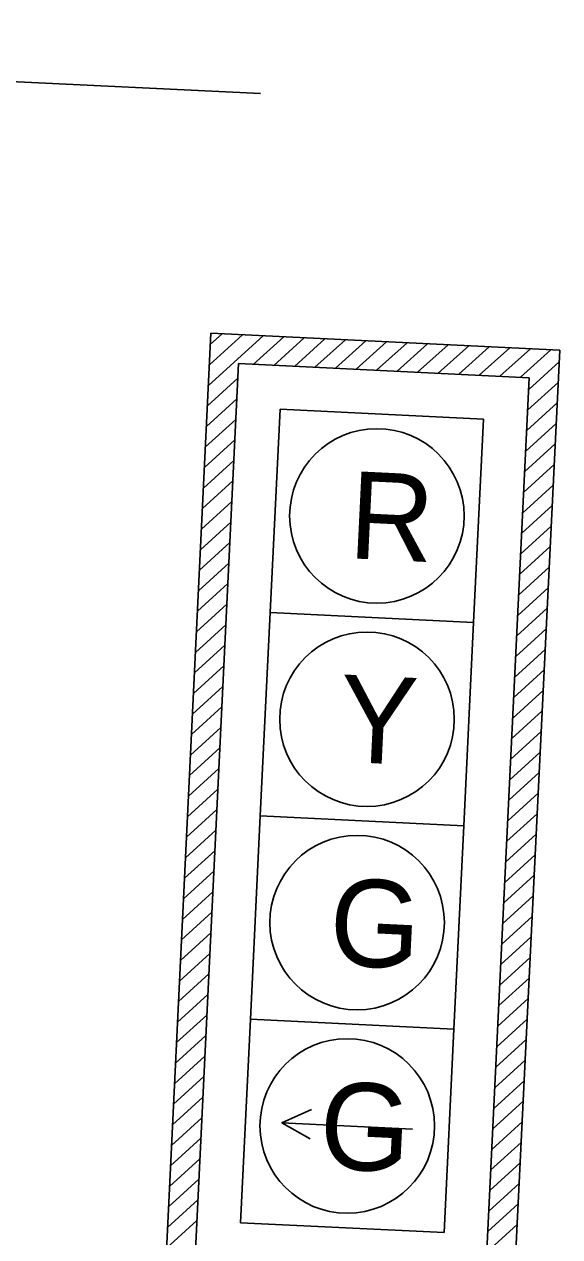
# Model space of a CAD drawing. Extents: x 662220 to 671027, y 641390 to 743815.
# Drawn here: x 662575.9 to 662612.7, y 642642.2 to 642725.6 of the extents above; entities that cross this region are included whole.
import ezdxf

# ---------------------------------------------------------------- set-up
doc = ezdxf.new("R2010")
doc.units = 0
doc.layers.add('R_Proposed Road Annot', color=7, linetype='Continuous')

msp = doc.modelspace()

# ---------------------------------------------------------------- linework, layer by layer
at = {"layer": 'R_Proposed Road Annot'}
for p, q in [((662494.01, 642725.551), (662592.08, 642720.789)), ((662588.684, 642704.307), (662585.483, 642638.385)), ((662588.51, 642700.718), (662592.273, 642704.133)), ((662588.578, 642702.131), (662590.86, 642704.201)), ((662588.647, 642703.543), (662589.448, 642704.27)), ((662612.656, 642703.143), (662588.684, 642704.307)), ((662591.591, 642702.163), (662593.685, 642704.064)), ((662593.003, 642702.095), (662595.098, 642703.995)), ((662594.416, 642702.026), (662596.51, 642703.927)), ((662595.828, 642701.958), (662597.923, 642703.858)), ((662597.241, 642701.889), (662599.335, 642703.79)), ((662598.653, 642701.82), (662600.748, 642703.721)), ((662600.066, 642701.752), (662602.16, 642703.652)), ((662601.478, 642701.683), (662603.573, 642703.584)), ((662602.891, 642701.615), (662604.986, 642703.515)), ((662604.303, 642701.546), (662606.398, 642703.447)), ((662605.716, 642701.477), (662607.811, 642703.378)), ((662607.129, 642701.409), (662609.223, 642703.309)), ((662608.541, 642701.34), (662610.636, 642703.241)), ((662609.454, 642637.22), (662612.656, 642703.143)), ((662609.954, 642701.272), (662612.048, 642703.172)), ((662610.522, 642700.437), (662612.617, 642702.338)), ((662588.441, 642699.306), (662590.536, 642701.206)), ((662610.453, 642699.024), (662612.548, 642700.925)), ((662588.372, 642697.893), (662590.467, 642699.794)), ((662610.385, 642697.612), (662612.479, 642699.512)), ((662593.435, 642699.07), (662592.756, 642685.087)), ((662593.435, 642699.07), (662607.419, 642698.391)), ((662588.304, 642696.48), (662590.398, 642698.381)), ((662607.419, 642698.391), (662606.74, 642684.408)), ((662610.316, 642696.199), (662612.411, 642698.1)), ((662588.235, 642695.068), (662590.33, 642696.969)), ((662610.248, 642694.787), (662612.342, 642696.687)), ((662588.167, 642693.655), (662590.261, 642695.556)), ((662610.179, 642693.374), (662612.274, 642695.275)), ((662588.098, 642692.243), (662590.193, 642694.143)), ((662610.11, 642691.962), (662612.205, 642693.862)), ((662588.029, 642690.83), (662590.124, 642692.731)), ((662610.042, 642690.549), (662612.136, 642692.45)), ((662587.961, 642689.418), (662590.056, 642691.318)), ((662609.973, 642689.137), (662612.068, 642691.037)), ((662587.892, 642688.005), (662589.987, 642689.906)), ((662609.905, 642687.724), (662611.999, 642689.625)), ((662587.824, 642686.593), (662589.918, 642688.493)), ((662609.836, 642686.311), (662611.931, 642688.212)), ((662587.755, 642685.18), (662589.85, 642687.081)), ((662609.767, 642684.899), (662611.862, 642686.8)), ((662587.687, 642683.768), (662589.781, 642685.668)), ((662609.699, 642683.486), (662611.793, 642685.387)), ((662592.756, 642685.087), (662592.077, 642671.103)), ((662592.756, 642685.087), (662606.74, 642684.408)), ((662587.618, 642682.355), (662589.713, 642684.256)), ((662606.74, 642684.408), (662606.061, 642670.424)), ((662609.63, 642682.074), (662611.725, 642683.974)), ((662587.549, 642680.942), (662589.644, 642682.843)), ((662609.562, 642680.661), (662611.656, 642682.562)), ((662587.481, 642679.53), (662589.575, 642681.431)), ((662609.493, 642679.249), (662611.588, 642681.149)), ((662587.412, 642678.117), (662589.507, 642680.018)), ((662609.424, 642677.836), (662611.519, 642679.737)), ((662587.344, 642676.705), (662589.438, 642678.605)), ((662609.356, 642676.424), (662611.45, 642678.324)), ((662587.275, 642675.292), (662589.37, 642677.193)), ((662609.287, 642675.011), (662611.382, 642676.912)), ((662587.206, 642673.88), (662589.301, 642675.78)), ((662609.219, 642673.598), (662611.313, 642675.499)), ((662587.138, 642672.467), (662589.232, 642674.368)), ((662609.15, 642672.186), (662611.245, 642674.087)), ((662587.069, 642671.055), (662589.164, 642672.955)), ((662609.081, 642670.773), (662611.176, 642672.674)), ((662587.001, 642669.642), (662589.095, 642671.543)), ((662592.077, 642671.103), (662591.398, 642657.12)), ((662592.077, 642671.103), (662606.061, 642670.424)), ((662609.013, 642669.361), (662611.108, 642671.261)), ((662606.061, 642670.424), (662605.382, 642656.441)), ((662586.932, 642668.229), (662589.027, 642670.13)), ((662608.944, 642667.948), (662611.039, 642669.849)), ((662586.863, 642666.817), (662588.958, 642668.718)), ((662608.876, 642666.536), (662610.97, 642668.436)), ((662586.795, 642665.404), (662588.889, 642667.305)), ((662608.807, 642665.123), (662610.902, 642667.024)), ((662586.726, 642663.992), (662588.821, 642665.892)), ((662608.738, 642663.711), (662610.833, 642665.611)), ((662586.658, 642662.579), (662588.752, 642664.48)), ((662608.67, 642662.298), (662610.765, 642664.199)), ((662586.589, 642661.167), (662588.684, 642663.067)), ((662608.601, 642660.886), (662610.696, 642662.786)), ((662586.52, 642659.754), (662588.615, 642661.655)), ((662608.533, 642659.473), (662610.627, 642661.374)), ((662586.452, 642658.342), (662588.546, 642660.242)), ((662608.464, 642658.06), (662610.559, 642659.961)), ((662586.383, 642656.929), (662588.478, 642658.83)), ((662608.396, 642656.648), (662610.49, 642658.549)), ((662586.315, 642655.517), (662588.409, 642657.417)), ((662591.398, 642657.12), (662590.719, 642643.136)), ((662591.398, 642657.12), (662605.382, 642656.441)), ((662608.327, 642655.235), (662610.422, 642657.136)), ((662605.382, 642656.441), (662604.703, 642642.457)), ((662586.246, 642654.104), (662588.341, 642656.005)), ((662608.258, 642653.823), (662610.353, 642655.723)), ((662586.177, 642652.691), (662588.272, 642654.592)), ((662608.19, 642652.41), (662610.284, 642654.311)), ((662586.109, 642651.279), (662588.204, 642653.18)), ((662608.121, 642650.998), (662610.216, 642652.898)), ((662586.04, 642649.866), (662588.135, 642651.767)), ((662608.053, 642649.585), (662610.147, 642651.486)), ((662585.972, 642648.454), (662588.066, 642650.354)), ((662602.545, 642649.57), (662593.556, 642650.007)), ((662607.984, 642648.173), (662610.079, 642650.073)), ((662585.903, 642647.041), (662587.998, 642648.942)), ((662607.915, 642646.76), (662610.01, 642648.661)), ((662585.835, 642645.629), (662587.929, 642647.529)), ((662607.847, 642645.347), (662609.941, 642647.248)), ((662585.766, 642644.216), (662587.861, 642646.117)), ((662607.778, 642643.935), (662609.873, 642645.836)), ((662585.697, 642642.804), (662587.792, 642644.704)), ((662607.71, 642642.522), (662609.804, 642644.423)), ((662585.629, 642641.391), (662587.723, 642643.292)), ((662590.719, 642643.136), (662604.703, 642642.457)), ((662607.641, 642641.11), (662609.736, 642643.01))]:
    msp.add_line(p, q, dxfattribs=at)
msp.add_lwpolyline([(662610.561, 642701.242), (662590.585, 642702.212), (662587.577, 642640.285), (662607.554, 642639.315)], close=True, dxfattribs=at)
msp.add_lwpolyline([(662595.602, 642650.908), (662593.556, 642650.007), (662595.505, 642648.911)], dxfattribs=at)
for centre in [(662600.088, 642691.739), (662599.409, 642677.755), (662598.73, 642663.772), (662598.051, 642649.788)]:
    msp.add_circle(centre, 6, dxfattribs=at)

# ---------------------------------------------------------------- texts
for s, p in [('R', (662598.079, 642688.834)), ('Y', (662597.377, 642674.852)), ('G', (662596.72, 642660.867)), ('G', (662596.041, 642646.883))]:
    msp.add_text(s, height=5.998, rotation=357.21992, dxfattribs=at).set_placement(p)

doc.saveas('drawing.dxf')
